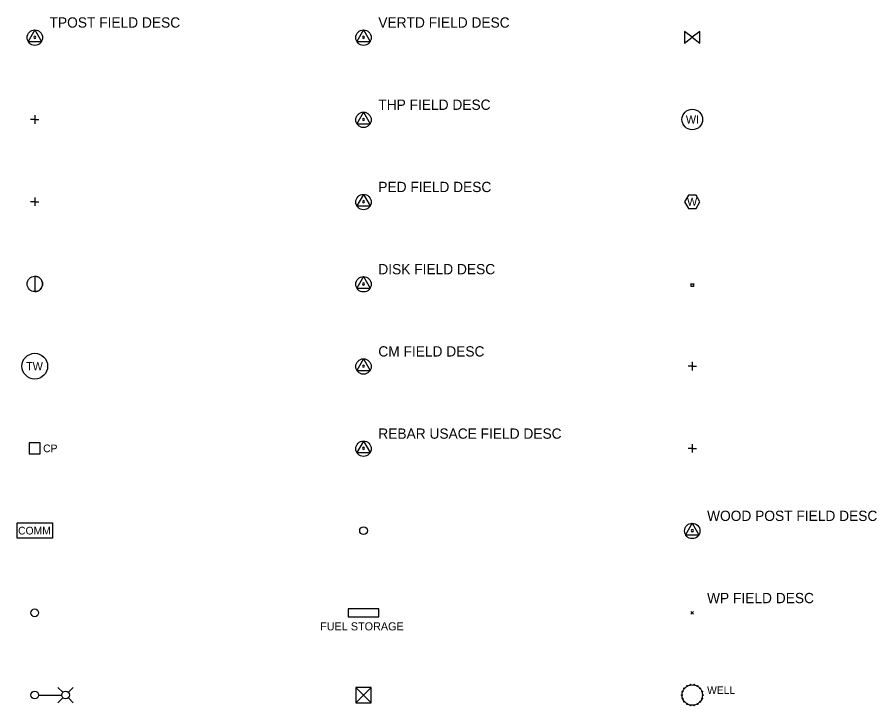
# Model space of a CAD drawing. Extents: x 91 to 2906, y -24 to 912.
# Drawn here: x 2289 to 2812, y 493 to 912 of the extents above; entities that cross this region are included whole.
import ezdxf

# ---------------------------------------------------------------- set-up
doc = ezdxf.new("R2010")
doc.units = 0
for name, color, linetype in [('B-SAMP-VERT', 7, 'Continuous'), ('V-AFLD-DEVC', 7, 'Continuous'), ('V-COMM-EQPM', 7, 'Continuous'), ('V-CTRL-BMRK', 7, 'Continuous'), ('V-CTRL-VERT', 7, 'Continuous'), ('V-FUEL-TANK', 7, 'Continuous'), ('V-POWR-POLE', 7, 'Continuous'), ('V-SITE-OTLN', 7, 'Continuous'), ('V-SITE-STRC', 7, 'Continuous'), ('V-SSWR-SIGN', 7, 'Continuous'), ('V-SURV-DATA', 7, 'Continuous'), ('V-TOPO-WATR', 7, 'Continuous'), ('V-UTIL-DEVC', 7, 'Continuous'), ('V-UTIL-IDEN', 7, 'Continuous'), ('V-WATR-DEVC', 7, 'Continuous'), ('V-WATR-METR', 7, 'Continuous'), ('V-WATR-VALT', 7, 'Continuous')]:
    doc.layers.add(name, color=color, linetype=linetype)

msp = doc.modelspace()

# ---------------------------------------------------------------- linework, layer by layer
at = {"layer": 'B-SAMP-VERT'}
msp.add_circle((2300, 700), 7.81, dxfattribs=at)
at = {"layer": 'V-AFLD-DEVC'}
msp.add_line((2300, 754.69), (2300, 745.31), dxfattribs=at)
msp.add_circle((2300, 750), 4.69, dxfattribs=at)
msp.add_arc((2300, 750), 4.69, 270, 90, dxfattribs=at)
at = {"layer": 'V-COMM-EQPM'}
for points in [[(2296.67, 646.67), (2303.33, 646.67), (2303.33, 653.33), (2296.67, 653.33)], [(2289.3, 604.69), (2310.7, 604.69), (2310.7, 595.31), (2289.3, 595.31)]]:
    msp.add_lwpolyline(points, close=True, dxfattribs=at)
at = {"layer": 'V-FUEL-TANK'}
msp.add_lwpolyline([(2490.62, 552.34), (2490.62, 547.66), (2509.38, 547.66), (2509.38, 552.34)], close=True, dxfattribs=at)
at = {"layer": 'V-POWR-POLE'}
for centre in [(2500, 600), (2300, 550)]:
    msp.add_circle(centre, 2.34, dxfattribs=at)
at = {"layer": 'V-SITE-OTLN'}
for p, q in [((2300, 802.55), (2300, 797.46)), ((2300, 800), (2297.46, 800)), ((2300, 800), (2302.55, 800)), ((2317.09, 501.66), (2314.06, 504.69)), ((2320.41, 501.66), (2323.44, 504.69)), ((2302.34, 500), (2316.41, 500)), ((2317.09, 498.34), (2314.06, 495.31)), ((2320.41, 498.34), (2323.44, 495.31))]:
    msp.add_line(p, q, dxfattribs=at)
for centre in [(2300, 500), (2318.75, 500)]:
    msp.add_circle(centre, 2.34, dxfattribs=at)
at = {"layer": 'V-SITE-STRC'}
for p, q in [((2495.31, 495.31), (2504.69, 504.69)), ((2495.31, 504.69), (2504.69, 495.31))]:
    msp.add_line(p, q, dxfattribs=at)
msp.add_lwpolyline([(2495.31, 495.31), (2504.69, 495.31), (2504.69, 504.69), (2495.31, 504.69)], close=True, dxfattribs=at)
at = {"layer": 'V-SURV-DATA'}
for p, q in [((2300, 904.48), (2295.95, 897.46)), ((2300, 904.48), (2304.05, 897.46)), ((2500, 904.48), (2495.95, 897.46)), ((2500, 904.48), (2504.05, 897.46)), ((2295.95, 897.46), (2304.05, 897.46)), ((2495.95, 897.46), (2504.05, 897.46)), ((2500, 854.48), (2495.95, 847.46)), ((2500, 854.48), (2504.05, 847.46)), ((2495.95, 847.46), (2504.05, 847.46)), ((2500, 804.48), (2495.95, 797.46)), ((2500, 804.48), (2504.05, 797.46)), ((2495.95, 797.46), (2504.05, 797.46)), ((2500, 754.48), (2495.95, 747.46)), ((2500, 754.48), (2504.05, 747.46)), ((2495.95, 747.46), (2504.05, 747.46)), ((2500, 704.48), (2495.95, 697.46)), ((2500, 704.48), (2504.05, 697.46)), ((2495.95, 697.46), (2504.05, 697.46)), ((2500, 654.48), (2495.95, 647.46)), ((2500, 654.48), (2504.05, 647.46)), ((2495.95, 647.46), (2504.05, 647.46)), ((2700, 604.48), (2695.95, 597.46)), ((2700, 604.48), (2704.05, 597.46)), ((2695.95, 597.46), (2704.05, 597.46))]:
    msp.add_line(p, q, dxfattribs=at)
for centre in [(2300, 899.8), (2500, 899.8), (2500, 849.8), (2500, 799.8), (2500, 749.8), (2500, 699.8), (2500, 649.8), (2700, 599.8)]:
    msp.add_circle(centre, 4.69, dxfattribs=at)
for centre in [(2300, 900), (2500, 900), (2500, 850), (2500, 800), (2500, 750), (2500, 700), (2500, 650), (2700, 600)]:
    msp.add_arc(centre, 0.65, 92.2877, 90.5674, dxfattribs=at)
at = {"layer": 'V-TOPO-WATR'}
for p, q in [((2700, 650), (2697.46, 650)), ((2700, 652.55), (2700, 647.46)), ((2700, 650), (2702.55, 650))]:
    msp.add_line(p, q, dxfattribs=at)
at = {"layer": 'V-UTIL-DEVC'}
for p, q in [((2699.19, 549.17), (2700.84, 550.83)), ((2700.84, 549.17), (2699.19, 550.83)), ((2694.03, 502.17), (2694.03, 502.17)), ((2695.13, 504.08), (2695.13, 504.08)), ((2696.82, 505.5), (2696.82, 505.5)), ((2698.9, 506.25), (2698.9, 506.25)), ((2701.11, 506.25), (2701.11, 506.25)), ((2703.18, 505.5), (2703.18, 505.5)), ((2704.87, 504.08), (2704.87, 504.08)), ((2705.97, 502.17), (2705.97, 502.17)), ((2693.65, 500), (2693.65, 500)), ((2694.03, 497.82), (2694.03, 497.82)), ((2705.97, 497.82), (2705.97, 497.82)), ((2706.35, 500), (2706.35, 500)), ((2695.13, 495.91), (2695.13, 495.91)), ((2696.82, 494.5), (2696.82, 494.5)), ((2698.9, 493.75), (2698.9, 493.75)), ((2701.11, 493.75), (2701.11, 493.75)), ((2703.18, 494.5), (2703.18, 494.5)), ((2704.87, 495.91), (2704.87, 495.91))]:
    msp.add_line(p, q, dxfattribs=at)
for centre, radius in [((2694.03, 502.17), 0.282), ((2700, 500), 6.24), ((2695.14, 504.08), 0.282), ((2696.83, 505.5), 0.282), ((2698.9, 506.25), 0.282), ((2701.1, 506.25), 0.282), ((2703.18, 505.5), 0.282), ((2704.86, 504.08), 0.282), ((2705.97, 502.17), 0.282), ((2693.65, 500), 0.282), ((2694.03, 497.83), 0.282), ((2705.97, 497.83), 0.282), ((2706.35, 500), 0.282), ((2695.14, 495.92), 0.282), ((2696.83, 494.5), 0.282), ((2698.9, 493.75), 0.282), ((2701.1, 493.75), 0.282), ((2703.18, 494.5), 0.282), ((2704.86, 495.92), 0.282)]:
    msp.add_circle(centre, radius, dxfattribs=at)
at = {"layer": 'V-UTIL-IDEN'}
for p, q in [((2300, 852.55), (2300, 847.46)), ((2300, 850), (2297.46, 850)), ((2300, 850), (2302.55, 850))]:
    msp.add_line(p, q, dxfattribs=at)
at = {"layer": 'V-WATR-DEVC'}
for p, q in [((2698.9, 750), (2701.1, 750)), ((2700, 702.55), (2700, 697.46)), ((2700, 700), (2697.46, 700)), ((2700, 700), (2702.55, 700))]:
    msp.add_line(p, q, dxfattribs=at)
msp.add_lwpolyline([(2700.75, 749.65), (2700.75, 748.5), (2699.25, 748.5), (2699.25, 749.65)], dxfattribs=at)
msp.add_circle((2700, 850), 6.25, dxfattribs=at)
for centre, start, end in [((2698.9, 749.65), 0, 90), ((2701.1, 749.65), 90, 180)]:
    msp.add_arc(centre, 0.349, start, end, dxfattribs=at)
at = {"layer": 'V-WATR-METR'}
msp.add_lwpolyline([(2702.34, 795.94), (2704.69, 800), (2702.34, 804.06), (2697.66, 804.06), (2695.31, 800), (2697.66, 795.94)], close=True, dxfattribs=at)
at = {"layer": 'V-WATR-VALT'}
for p, q in [((2700, 900), (2695.32, 903.53)), ((2695.32, 903.53), (2695.32, 896.47)), ((2695.32, 896.47), (2700, 900)), ((2704.69, 903.52), (2700, 900)), ((2700, 900), (2704.69, 896.48)), ((2704.69, 896.48), (2704.69, 903.52))]:
    msp.add_line(p, q, dxfattribs=at)

# ---------------------------------------------------------------- texts
at = {"layer": 'B-SAMP-VERT'}
msp.add_text('TW', height=4.921, dxfattribs=at).set_placement((2294.69, 697.54))
at = {"layer": 'V-COMM-EQPM'}
for s, height, p in [('CP', 4.687, (2305.1, 647.66)), ('COMM', 4.692, (2289.87, 597.65))]:
    msp.add_text(s, height=height, dxfattribs=at).set_placement(p)
at = {"layer": 'V-CTRL-BMRK'}
for s, p in [('THP FIELD DESC', (2509, 855.87)), ('PED FIELD DESC', (2509, 805.87)), ('CM FIELD DESC', (2509, 705.87))]:
    msp.add_text(s, height=6.252, dxfattribs=at).set_placement(p)
at = {"layer": 'V-CTRL-VERT'}
msp.add_text('VERTD FIELD DESC', height=6.252, dxfattribs=at).set_placement((2509, 905.87))
at = {"layer": 'V-FUEL-TANK'}
msp.add_text('FUEL STORAGE', height=4.9213, dxfattribs=at).set_placement((2473.63, 539.32))
at = {"layer": 'V-SSWR-SIGN'}
msp.add_text('WP FIELD DESC', height=6.252, dxfattribs=at).set_placement((2709, 555.87))
at = {"layer": 'V-SURV-DATA'}
for s, p in [('TPOST FIELD DESC', (2309, 905.87)), ('DISK FIELD DESC', (2509, 755.87)), ('REBAR USACE FIELD DESC', (2509, 655.87)), ('WOOD POST FIELD DESC', (2709, 605.87))]:
    msp.add_text(s, height=6.252, dxfattribs=at).set_placement(p)
at = {"layer": 'V-UTIL-DEVC'}
msp.add_text('WELL', height=4.68, dxfattribs=at).set_placement((2709.02, 500.63))
at = {"layer": 'V-WATR-DEVC'}
msp.add_text('WI', height=4.921, dxfattribs=at).set_placement((2696.11, 847.54))
at = {"layer": 'V-WATR-METR'}
msp.add_text('W', height=4.92, dxfattribs=at).set_placement((2696.79, 797.54))

doc.saveas('drawing.dxf')
